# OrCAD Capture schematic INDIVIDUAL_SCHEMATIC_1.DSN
size A; title: Individual_Schematic_1; note: Version1
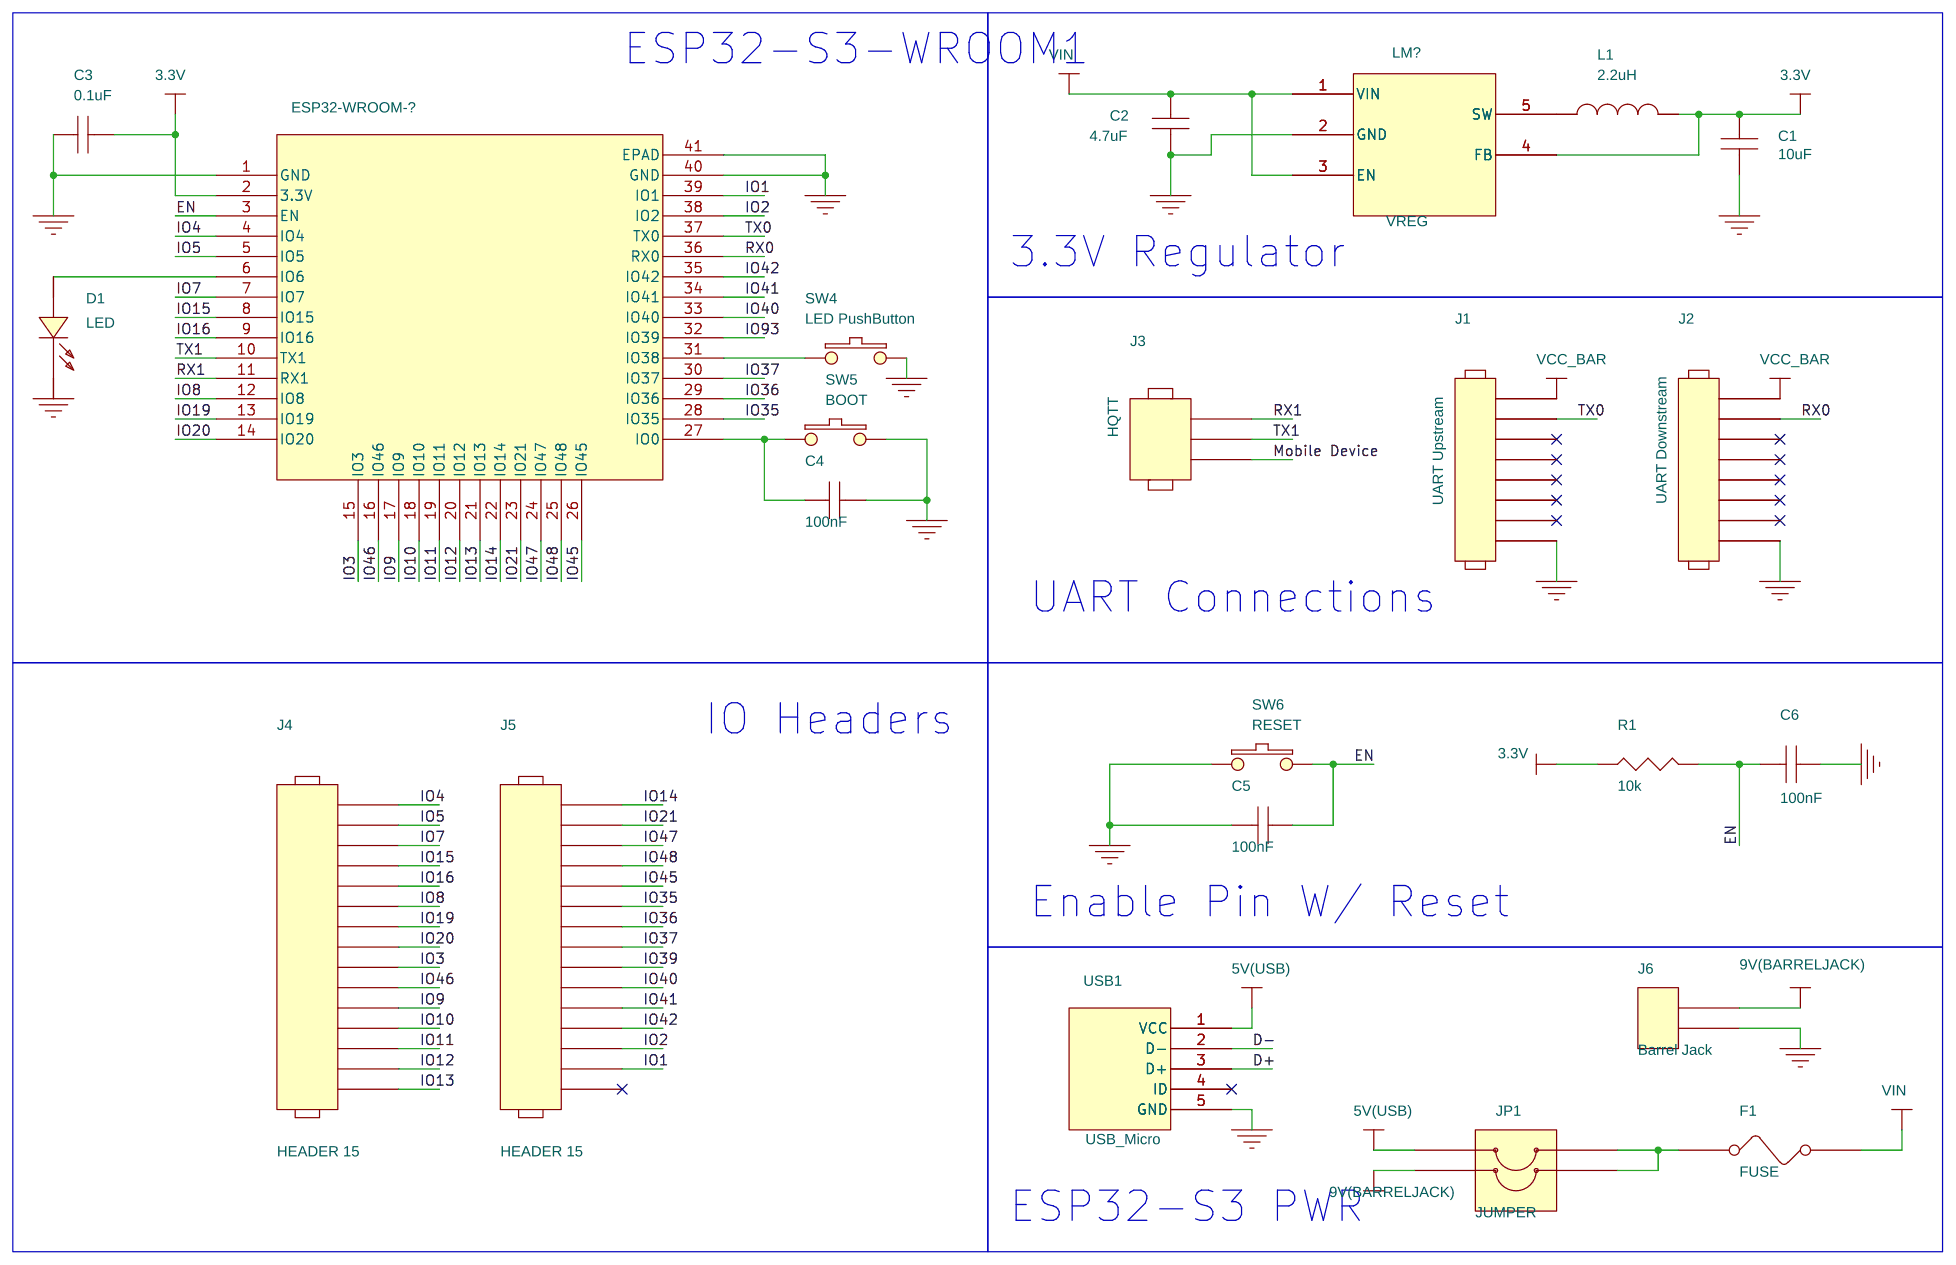
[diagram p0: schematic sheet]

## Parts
C1  10uF
C2  4.7uF
C3  0.1uF
C4  100nF
C5  100nF
C6  100nF
D1  LED
ESP32-WROOM-?#2  ESP32-S3-WROOM-1
F1  FUSE
J1  UART Upstream
J2  UART Downstream
J3  HQTT
J4  HEADER 15
J5  HEADER 15
J6  Barrel Jack
JP1  JUMPER
L1  2.2uH
LM?#1  VREG
R1  10k
SW4  LED PushButton
SW5  BOOT
SW6  RESET
USB1  USB_Micro

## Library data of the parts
C1-C6 = CAP_NP
D1 = LED
ESP32-WROOM-?#2 = ESP32-S3-WROOM-1_2
F1 = FUSE
J1 J2 = HEADER_8
J3 = HEADER_3
J4 J5 = HEADER_15
J6 = CONN_TRBLK_2
JP1 = JUMPER2
L1 = INDUCTOR
LM?#1 = VREG_0
R1 = RESISTOR
SW4-SW6 = SW_PUSHBUTTON
USB1 = USB_Micro

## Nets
3.3V: C1.1 C3.2 ESP32-WROOM-?#2.2(3.3V) J1.1 J2.1 L1.2 LM?#1.4(FB) R1.1
5V(USB): JP1.1 USB1.1(VCC)
9V(BarrelJack): J6.1 JP1.3
GND: C1.2 C2.2 C3.1 C4.2 C5.2 C6.1 D1.1(CATHODE) ESP32-WROOM-?#2.1(GND) ESP32-WROOM-?#2.40(GND) ESP32-WROOM-?#2.41(EPAD) J1.8 J2.8 J6.2 LM?#1.2(GND) SW4.2 SW5.2 SW6.2 USB1.5(GND)
VIN: C2.1 F1.2 LM?#1.1(VIN) LM?#1.3(EN)
D+: USB1.3(D+)
D-: USB1.2(D-)
EN: C5.1 C6.2 ESP32-WROOM-?#2.3(EN) R1.2 SW6.1
IO1: ESP32-WROOM-?#2.39(IO1) J5.14
IO2: ESP32-WROOM-?#2.38(IO2) J5.13
IO3: ESP32-WROOM-?#2.15(IO3) J4.9
IO4: ESP32-WROOM-?#2.4(IO4) J4.1
IO5: ESP32-WROOM-?#2.5(IO5) J4.2
IO7: ESP32-WROOM-?#2.7(IO7) J4.3
IO8: ESP32-WROOM-?#2.12(IO8) J4.6
IO9: ESP32-WROOM-?#2.17(IO9) J4.11
IO10: ESP32-WROOM-?#2.18(IO10) J4.12
IO11: ESP32-WROOM-?#2.19(IO11) J4.13
IO12: ESP32-WROOM-?#2.20(IO12) J4.14
IO13: ESP32-WROOM-?#2.21(IO13) J4.15
IO14: ESP32-WROOM-?#2.22(IO14) J5.1
IO15: ESP32-WROOM-?#2.8(IO15) J4.4
IO16: ESP32-WROOM-?#2.9(IO16) J4.5
IO19: ESP32-WROOM-?#2.13(IO19) J4.7
IO20: ESP32-WROOM-?#2.14(IO20) J4.8
IO21: ESP32-WROOM-?#2.23(IO21) J5.2
IO35: ESP32-WROOM-?#2.28(IO35) J5.6
IO36: ESP32-WROOM-?#2.29(IO36) J5.7
IO37: ESP32-WROOM-?#2.30(IO37) J5.8
IO39: J5.9
IO40: ESP32-WROOM-?#2.33(IO40) J5.10
IO41: ESP32-WROOM-?#2.34(IO41) J5.11
IO42: ESP32-WROOM-?#2.35(IO42) J5.12
IO45: ESP32-WROOM-?#2.26(IO45) J5.5
IO46: ESP32-WROOM-?#2.16(IO46) J4.10
IO47: ESP32-WROOM-?#2.24(IO47) J5.3
IO48: ESP32-WROOM-?#2.25(IO48) J5.4
IO93: ESP32-WROOM-?#2.32(IO39)
Mobile Device: J3.3
RX0: ESP32-WROOM-?#2.36(RX0) J2.2
RX1: ESP32-WROOM-?#2.11(RX1) J3.1
TX0: ESP32-WROOM-?#2.37(TX0) J1.2
TX1: ESP32-WROOM-?#2.10(TX1) J3.2
N01929: D1.2(ANODE) ESP32-WROOM-?#2.6(IO6)
N02099: ESP32-WROOM-?#2.31(IO38) SW4.1
N02657: C4.1 ESP32-WROOM-?#2.27(IO0) SW5.1
N06298: L1.1 LM?#1.5(SW)
N11737: F1.1 JP1.2 JP1.4

Not connected (* = marked no-connect by the designer): J1 3* 4* 5* 6* 7*; J2 3* 4* 5* 6* 7*; J5 15*; USB1 4(ID)*

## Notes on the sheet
- ESP32-S3-WROOM1
- 3.3V Regulator
- UART Connections
- IO Headers
- Enable Pin W/ Reset
- ESP32-S3 PWR
